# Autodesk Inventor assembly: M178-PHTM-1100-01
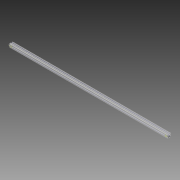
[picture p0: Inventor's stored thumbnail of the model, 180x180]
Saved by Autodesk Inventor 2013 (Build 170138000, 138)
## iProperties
Created: 2004-11
Part Number: M178-PHTM-1100-01
Document SubType Name: Assembly
Designer: Autodesk, Inc.
Manufacturer: Standard
Standards Organization: Custom
Description: PHANTOM, TABLE, TOP FRAME, CROSS BAR
Mass: 3224.28 g
Surface Area: 8325.34 cm^2
Volume: 1169.95 cm^3
Density: 2.75591 g/cm^3
CAGE: 1LJX3
Dept. ID: Product Design
Description #2: ---
Finish #1: ---
Finish #2: ---
Material ID: ---
Project Number: ---
Author: Autodesk, Inc.
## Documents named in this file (4)
- Z:\_DATEN\Test Station\Components\M178-100_Cross_Phantom.iam
- Z:\_DATEN\Test Station\Components\M178-1006.ipt
- Z:\_DATEN\Test Station\Components\20-004.iam
- C:\Users\kelleyb.ADS\Desktop\Samples MIGRATED 2009 224 RTM_1\Standard Parts\Test Station Content\Extrusions\40 Series Profiles.ipt
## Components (3 placed, 2 different names)
1. M178-1006:1
2. 20-004:1 [sub-assembly]
3. 20-004:2 [sub-assembly]
